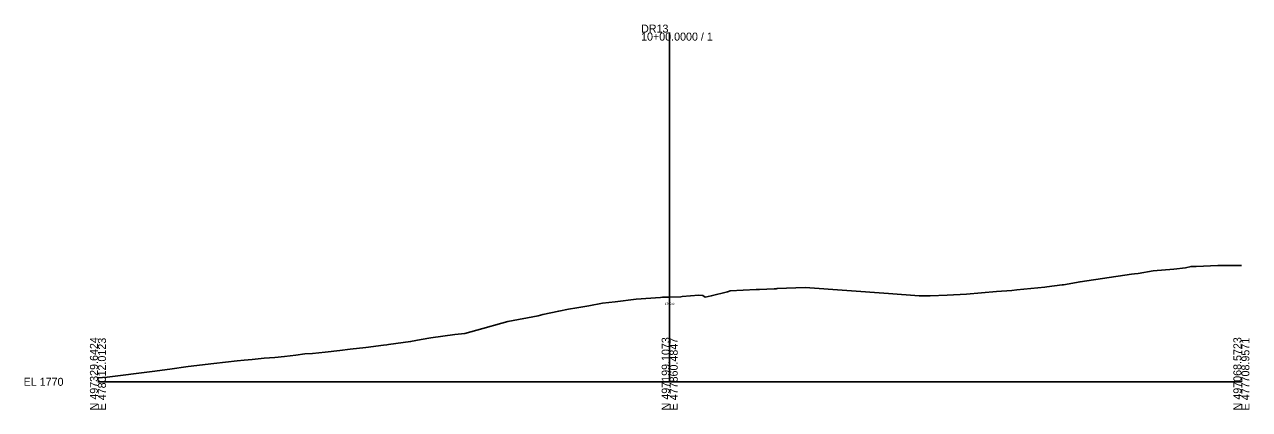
# Model space of a CAD drawing. Extents: x -26 to 403, y -10 to 2160.
# Drawn here: x -25.7 to 402.8, y -9.7 to 125 of the extents above; entities that cross this region are included whole.
import ezdxf

# ---------------------------------------------------------------- set-up
doc = ezdxf.new("R2010")
doc.units = 0
for name, color, linetype in [('Exist Cross Section Cell', 7, 'Continuous'), ('Exist XS Center Line Elevation Label', 7, 'Continuous'), ('Exist XS Ground Line', 7, 'Continuous'), ('Scratch_Level_5', 7, 'Continuous')]:
    doc.layers.add(name, color=color, linetype=linetype)

msp = doc.modelspace()

# ---------------------------------------------------------------- linework, layer by layer
at = {"layer": 'Exist Cross Section Cell'}
for p, q in [((200, 0), (200, 122.18)), ((0, 0), (200, 0)), ((200, 0), (400, 0))]:
    msp.add_line(p, q, dxfattribs=at)
at = {"layer": 'Exist XS Ground Line'}
msp.add_lwpolyline([(0, 1.34), (3.21, 1.66), (18.99, 3.56), (25.16, 4.37), (31.56, 5.31), (40.5, 6.39), (48.68, 7.28), (51.11, 7.57), (53.92, 7.77), (58.2, 8.26), (61.88, 8.54), (65.29, 8.89), (69.24, 9.29), (72.38, 9.73), (75.08, 9.96), (79.47, 10.39), (84.57, 10.92), (88.29, 11.38), (93.66, 12), (99.89, 12.78), (101.05, 12.96), (101.69, 13.05), (109.38, 14.09), (113.04, 14.79), (116.46, 15.42), (124.88, 16.59), (128.4, 16.93), (130.49, 17.52), (134.64, 18.66), (141.33, 20.57), (143.36, 21.15), (153.97, 23.14), (155.59, 23.58), (161.19, 24.74), (164.58, 25.37), (167.5, 25.85), (171.67, 26.56), (176.52, 27.47), (180.94, 28.02), (188.31, 28.92), (196.82, 29.55), (197.55, 29.56), (200, 29.64), (203.9, 29.76), (204.36, 29.82), (210.25, 30.33), (211.66, 30.2), (212.41, 29.61), (214.52, 30.05), (220.22, 31.46), (220.64, 31.57), (221.16, 31.8), (230.26, 32.28), (231.44, 32.34), (236.56, 32.55), (237.24, 32.58), (237.58, 32.6), (247.46, 32.96), (276.5, 30.91), (287.3, 30.07), (291.16, 30.11), (297.02, 30.29), (303.81, 30.67), (314.33, 31.54), (319.72, 31.95), (321.47, 32.21), (331.22, 33.11), (331.96, 33.2), (337.35, 33.91), (337.8, 33.96), (343.56, 34.99), (361.52, 37.67), (362.56, 37.83), (363.84, 37.94), (369.18, 38.85), (376.41, 39.37), (380.46, 39.93), (382.41, 40.39), (384.21, 40.38), (391.76, 40.66), (396.9, 40.69), (397.27, 40.69), (397.74, 40.72), (400, 40.73)], dxfattribs=at)
at = {"layer": 'Scratch_Level_5'}
msp.add_lwpolyline([(0, 1.34), (3.21, 1.66), (18.99, 3.56), (25.16, 4.37), (31.56, 5.31), (40.5, 6.39), (48.68, 7.28), (51.11, 7.57), (53.92, 7.77), (58.2, 8.26), (61.88, 8.54), (65.29, 8.89), (69.24, 9.29), (72.38, 9.73), (75.08, 9.96), (79.47, 10.39), (84.57, 10.92), (88.29, 11.38), (93.66, 12), (99.89, 12.78), (101.05, 12.96), (101.69, 13.05), (109.38, 14.09), (113.04, 14.79), (116.46, 15.42), (124.88, 16.59), (128.4, 16.93), (130.49, 17.52), (134.64, 18.66), (141.33, 20.57), (143.36, 21.15), (153.97, 23.14), (155.59, 23.58), (161.19, 24.74), (164.58, 25.37), (167.5, 25.85), (171.67, 26.56), (176.52, 27.47), (180.94, 28.02), (188.31, 28.92), (196.82, 29.55), (197.55, 29.56), (200, 29.64), (203.9, 29.76), (204.36, 29.82), (210.25, 30.33), (211.66, 30.2), (212.39, 29.65), (212.44, 29.53)], dxfattribs=at)

# ---------------------------------------------------------------- texts
at = {"layer": 'Exist Cross Section Cell'}
for s, p in [('DR13', (190, 122.18)), ('10+00.0000 / 1', (190, 119.38)), ('EL 1770', (-26, -1.4))]:
    msp.add_text(s, height=2.8, dxfattribs=at).set_placement(p)
for s, p in [('N 497329.6424', (0, -10)), ('E 478012.0123', (2.8, -10)), ('N 497199.1073', (200, -10)), ('E 477860.4847', (202.8, -10)), ('N 497068.5723', (400, -10)), ('E 477708.9571', (402.8, -10))]:
    msp.add_text(s, height=2.8, rotation=90, dxfattribs=at).set_placement(p)
at = {"layer": 'Exist XS Center Line Elevation Label'}
msp.add_text('1799.64', height=0.75, dxfattribs=at).set_placement((198.31, 26.89))

doc.saveas('drawing.dxf')
